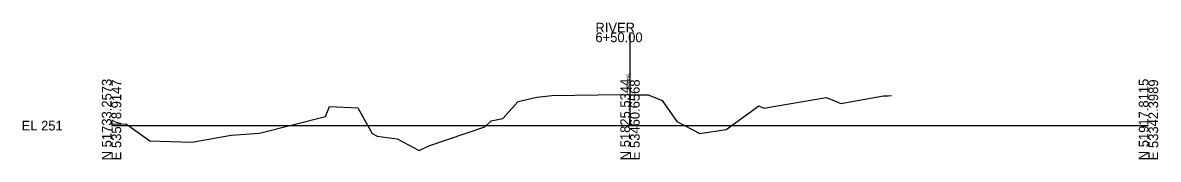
# Model space of a CAD drawing. Extents: x 5628 to 5956, y 92469 to 104012.
# Drawn here: x 5627.6 to 5956.2, y 95968.9 to 96008.3 of the extents above; entities that cross this region are included whole.
import ezdxf

# ---------------------------------------------------------------- set-up
doc = ezdxf.new("R2010")
doc.units = 0
for name, color, linetype in [('Level 10', 7, 'Continuous'), ('Level 60', 7, 'Continuous'), ('Level 63', 7, 'Continuous')]:
    doc.layers.add(name, color=color, linetype=linetype)

msp = doc.modelspace()

# ---------------------------------------------------------------- linework, layer by layer
at = {"layer": 'Level 60'}
for p, q in [((5776.34, 95986.82), (5780.75, 95987.34)), ((5780.75, 95987.34), (5800.65, 95987.56)), ((5800.65, 95987.56), (5803.34, 95987.52)), ((5803.34, 95987.52), (5808.57, 95987.45)), ((5808.57, 95987.45), (5812.6, 95985.88)), ((5876.63, 95987.17), (5878.06, 95987.24)), ((5878.06, 95987.24), (5878.95, 95987.25)), ((5715.21, 95981.24), (5716.39, 95984.08)), ((5716.39, 95984.08), (5724.59, 95983.78)), ((5766.56, 95980.62), (5771.01, 95985.58)), ((5771.01, 95985.58), (5776.34, 95986.82)), ((5812.6, 95985.88), (5816.92, 95979.78)), ((5831.14, 95977.47), (5840.62, 95984.31)), ((5840.62, 95984.31), (5842.04, 95983.6)), ((5842.04, 95983.6), (5860.13, 95986.69)), ((5860.13, 95986.69), (5862.3, 95985.82)), ((5862.3, 95985.82), (5864.29, 95985)), ((5864.29, 95985), (5876.63, 95987.17)), ((5696.11, 95976.4), (5715.21, 95981.24)), ((5724.59, 95983.78), (5728.78, 95976.33)), ((5763.15, 95980.03), (5766.56, 95980.62)), ((5653.34, 95979.07), (5657.63, 95979)), ((5657.63, 95979), (5664.38, 95974.23)), ((5745.18, 95972.76), (5761.31, 95978.29)), ((5761.31, 95978.29), (5763.15, 95980.03)), ((5816.92, 95979.78), (5823.58, 95976.29)), ((5823.58, 95976.29), (5831.14, 95977.47)), ((5664.38, 95974.23), (5676.54, 95973.83)), ((5676.54, 95973.83), (5687.93, 95975.85)), ((5687.93, 95975.85), (5696.11, 95976.4)), ((5728.78, 95976.33), (5730.18, 95975.6)), ((5730.18, 95975.6), (5735.93, 95974.75)), ((5735.93, 95974.75), (5742.35, 95971.45)), ((5742.35, 95971.45), (5745.18, 95972.76))]:
    msp.add_line(p, q, dxfattribs=at)
at = {"layer": 'Level 63'}
for p, q in [((5803.34, 95978.6), (5803.34, 96005.48)), ((5653.34, 95978.6), (5803.34, 95978.6)), ((5803.34, 95978.6), (5953.34, 95978.6))]:
    msp.add_line(p, q, dxfattribs=at)

# ---------------------------------------------------------------- texts
at = {"layer": 'Level 10'}
msp.add_text('255.46', height=1.2, rotation=90, dxfattribs=at).set_placement((5803.54, 95988.52))
at = {"layer": 'Level 63'}
for s, p in [('RIVER', (5793.34, 96005.48)), ('6+50.00', (5793.34, 96002.68)), ('EL 251', (5627.34, 95977.2))]:
    msp.add_text(s, height=2.8, dxfattribs=at).set_placement(p)
for s, p in [('N 51733.2573', (5653.34, 95968.59)), ('E 53578.9147', (5656.14, 95968.6)), ('N 51825.5344', (5803.34, 95968.6)), ('E 53460.6568', (5806.14, 95968.6)), ('N 51917.8115', (5953.34, 95968.6)), ('E 53342.3989', (5956.14, 95968.6))]:
    msp.add_text(s, height=2.8, rotation=90, dxfattribs=at).set_placement(p)

doc.saveas('drawing.dxf')
